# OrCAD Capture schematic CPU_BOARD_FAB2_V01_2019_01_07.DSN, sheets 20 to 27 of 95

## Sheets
20 071 ISOLATOR_1: size B
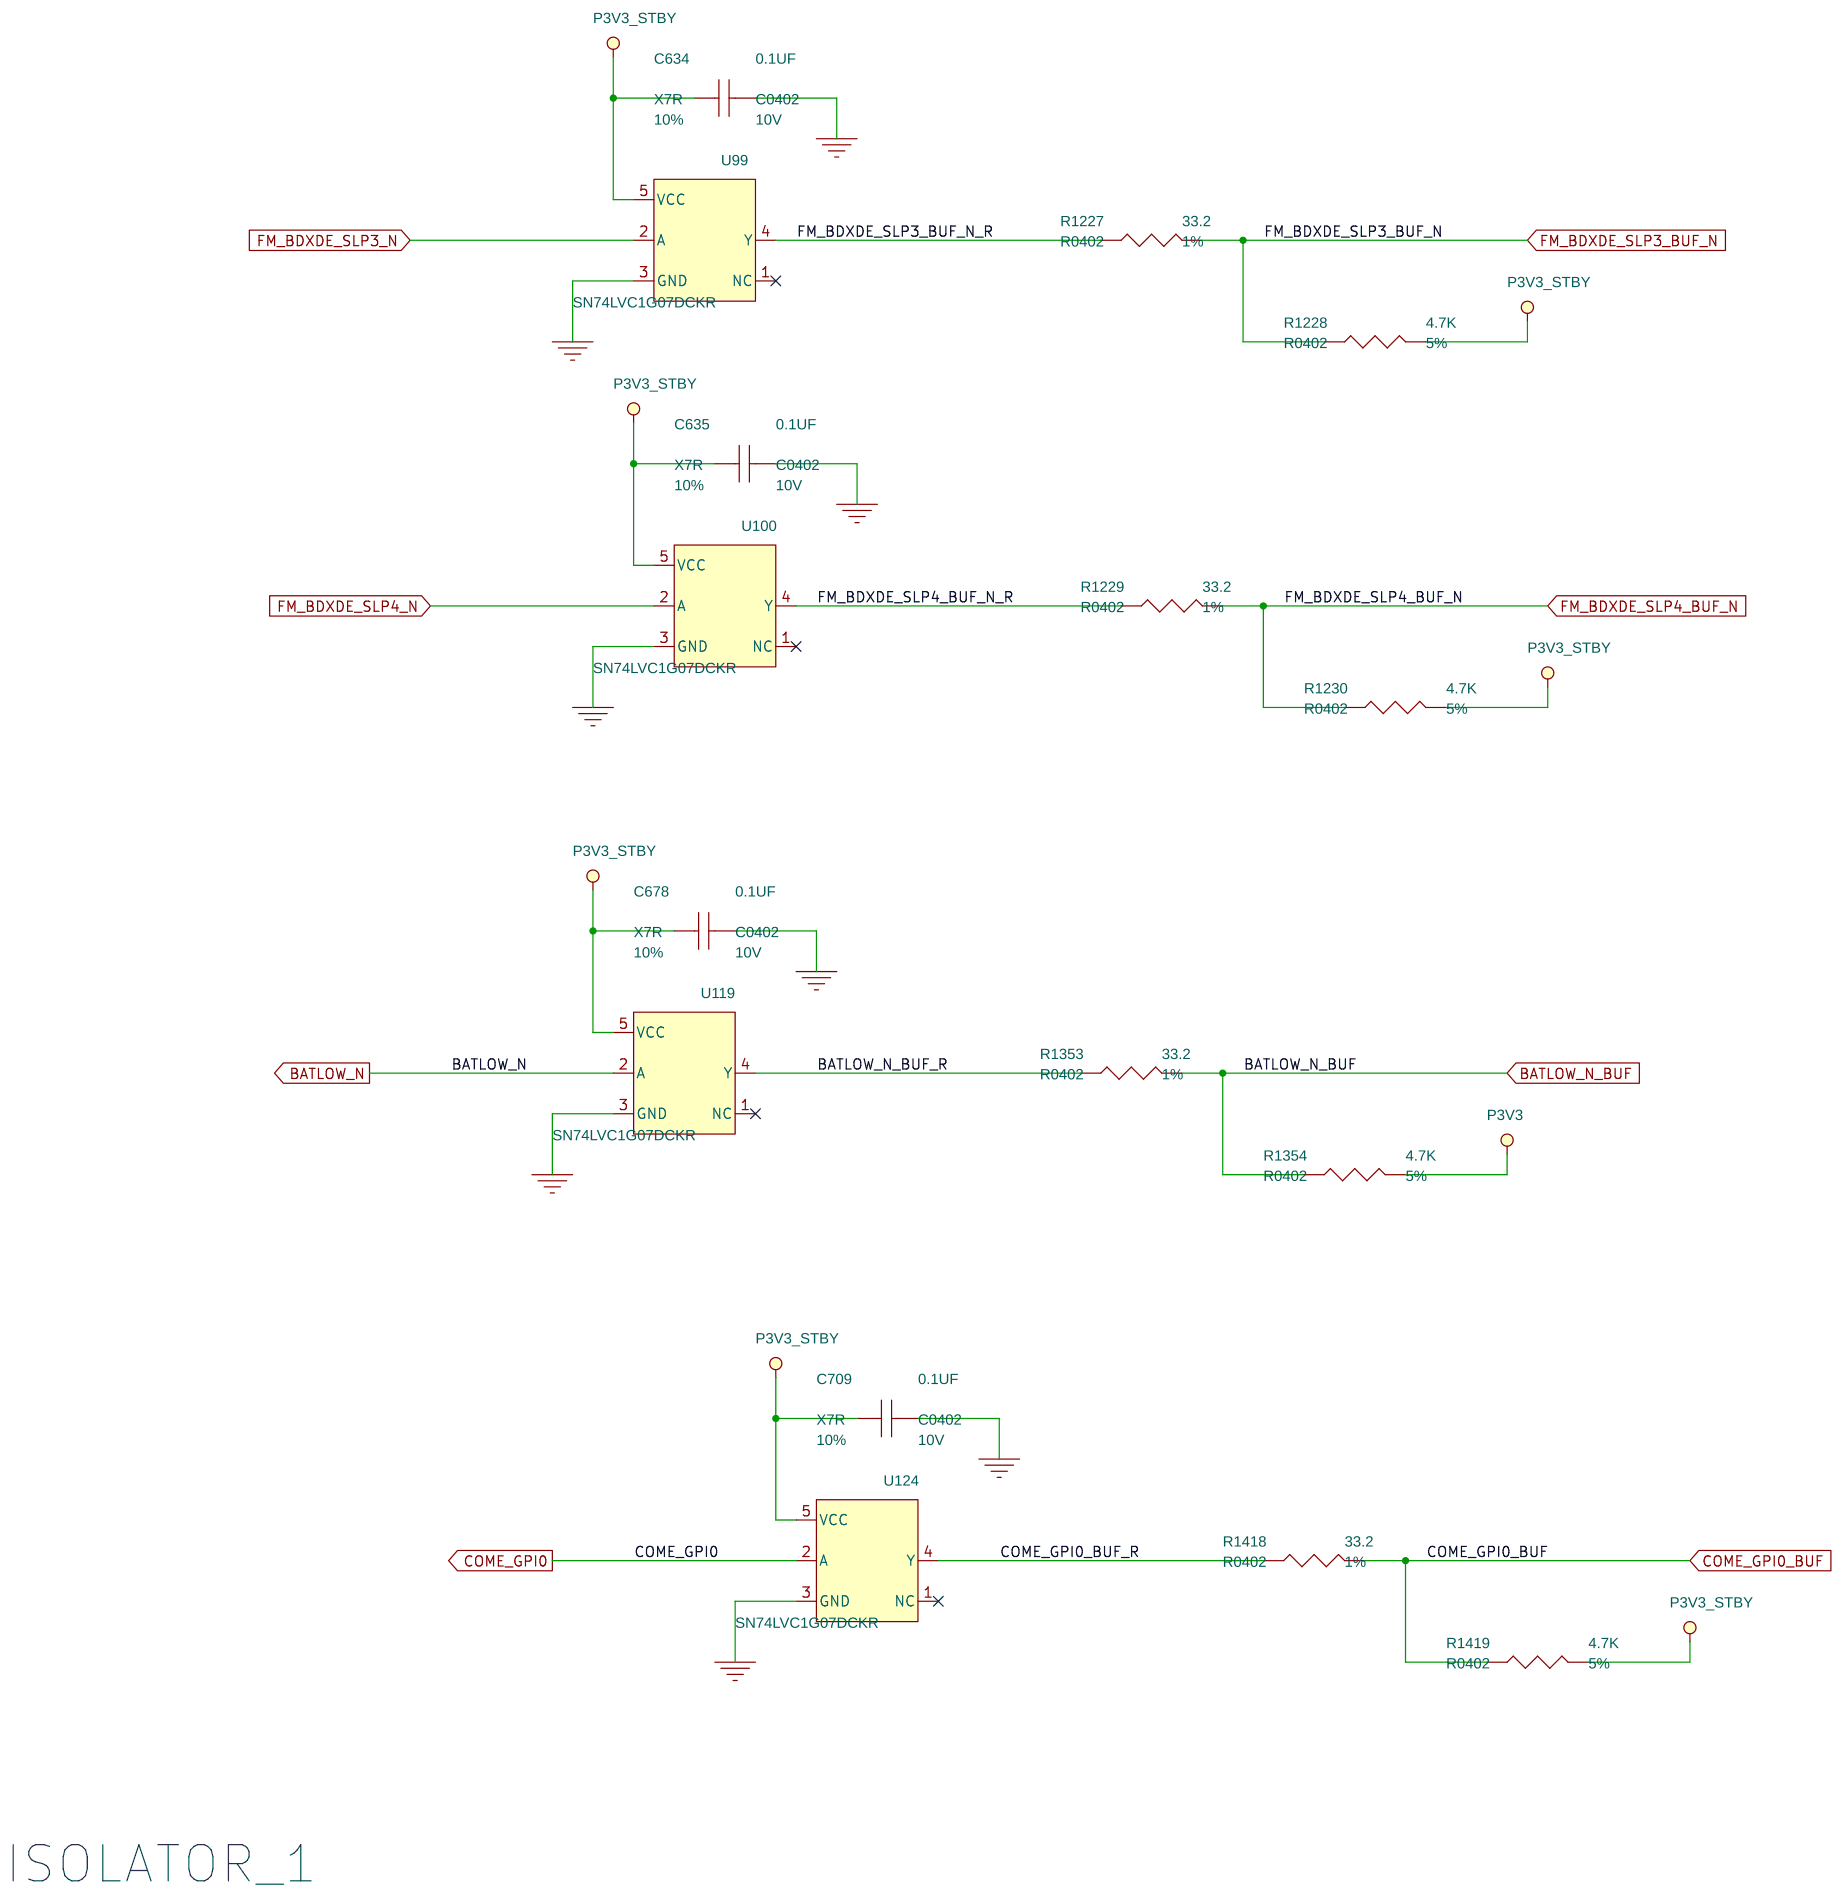
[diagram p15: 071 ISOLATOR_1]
21 015 BLANK
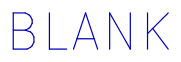
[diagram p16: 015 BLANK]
22 089 PV_DDR_VTTAB: size B
23 088 PV_VDDRAB_2: size B
24 087 PV_VDDRAB_1: size C
25 081 P2V5_VPP: size B
26 082 PVCCKRHV: size B
27 080 PVCCSCFUSESUS: size B
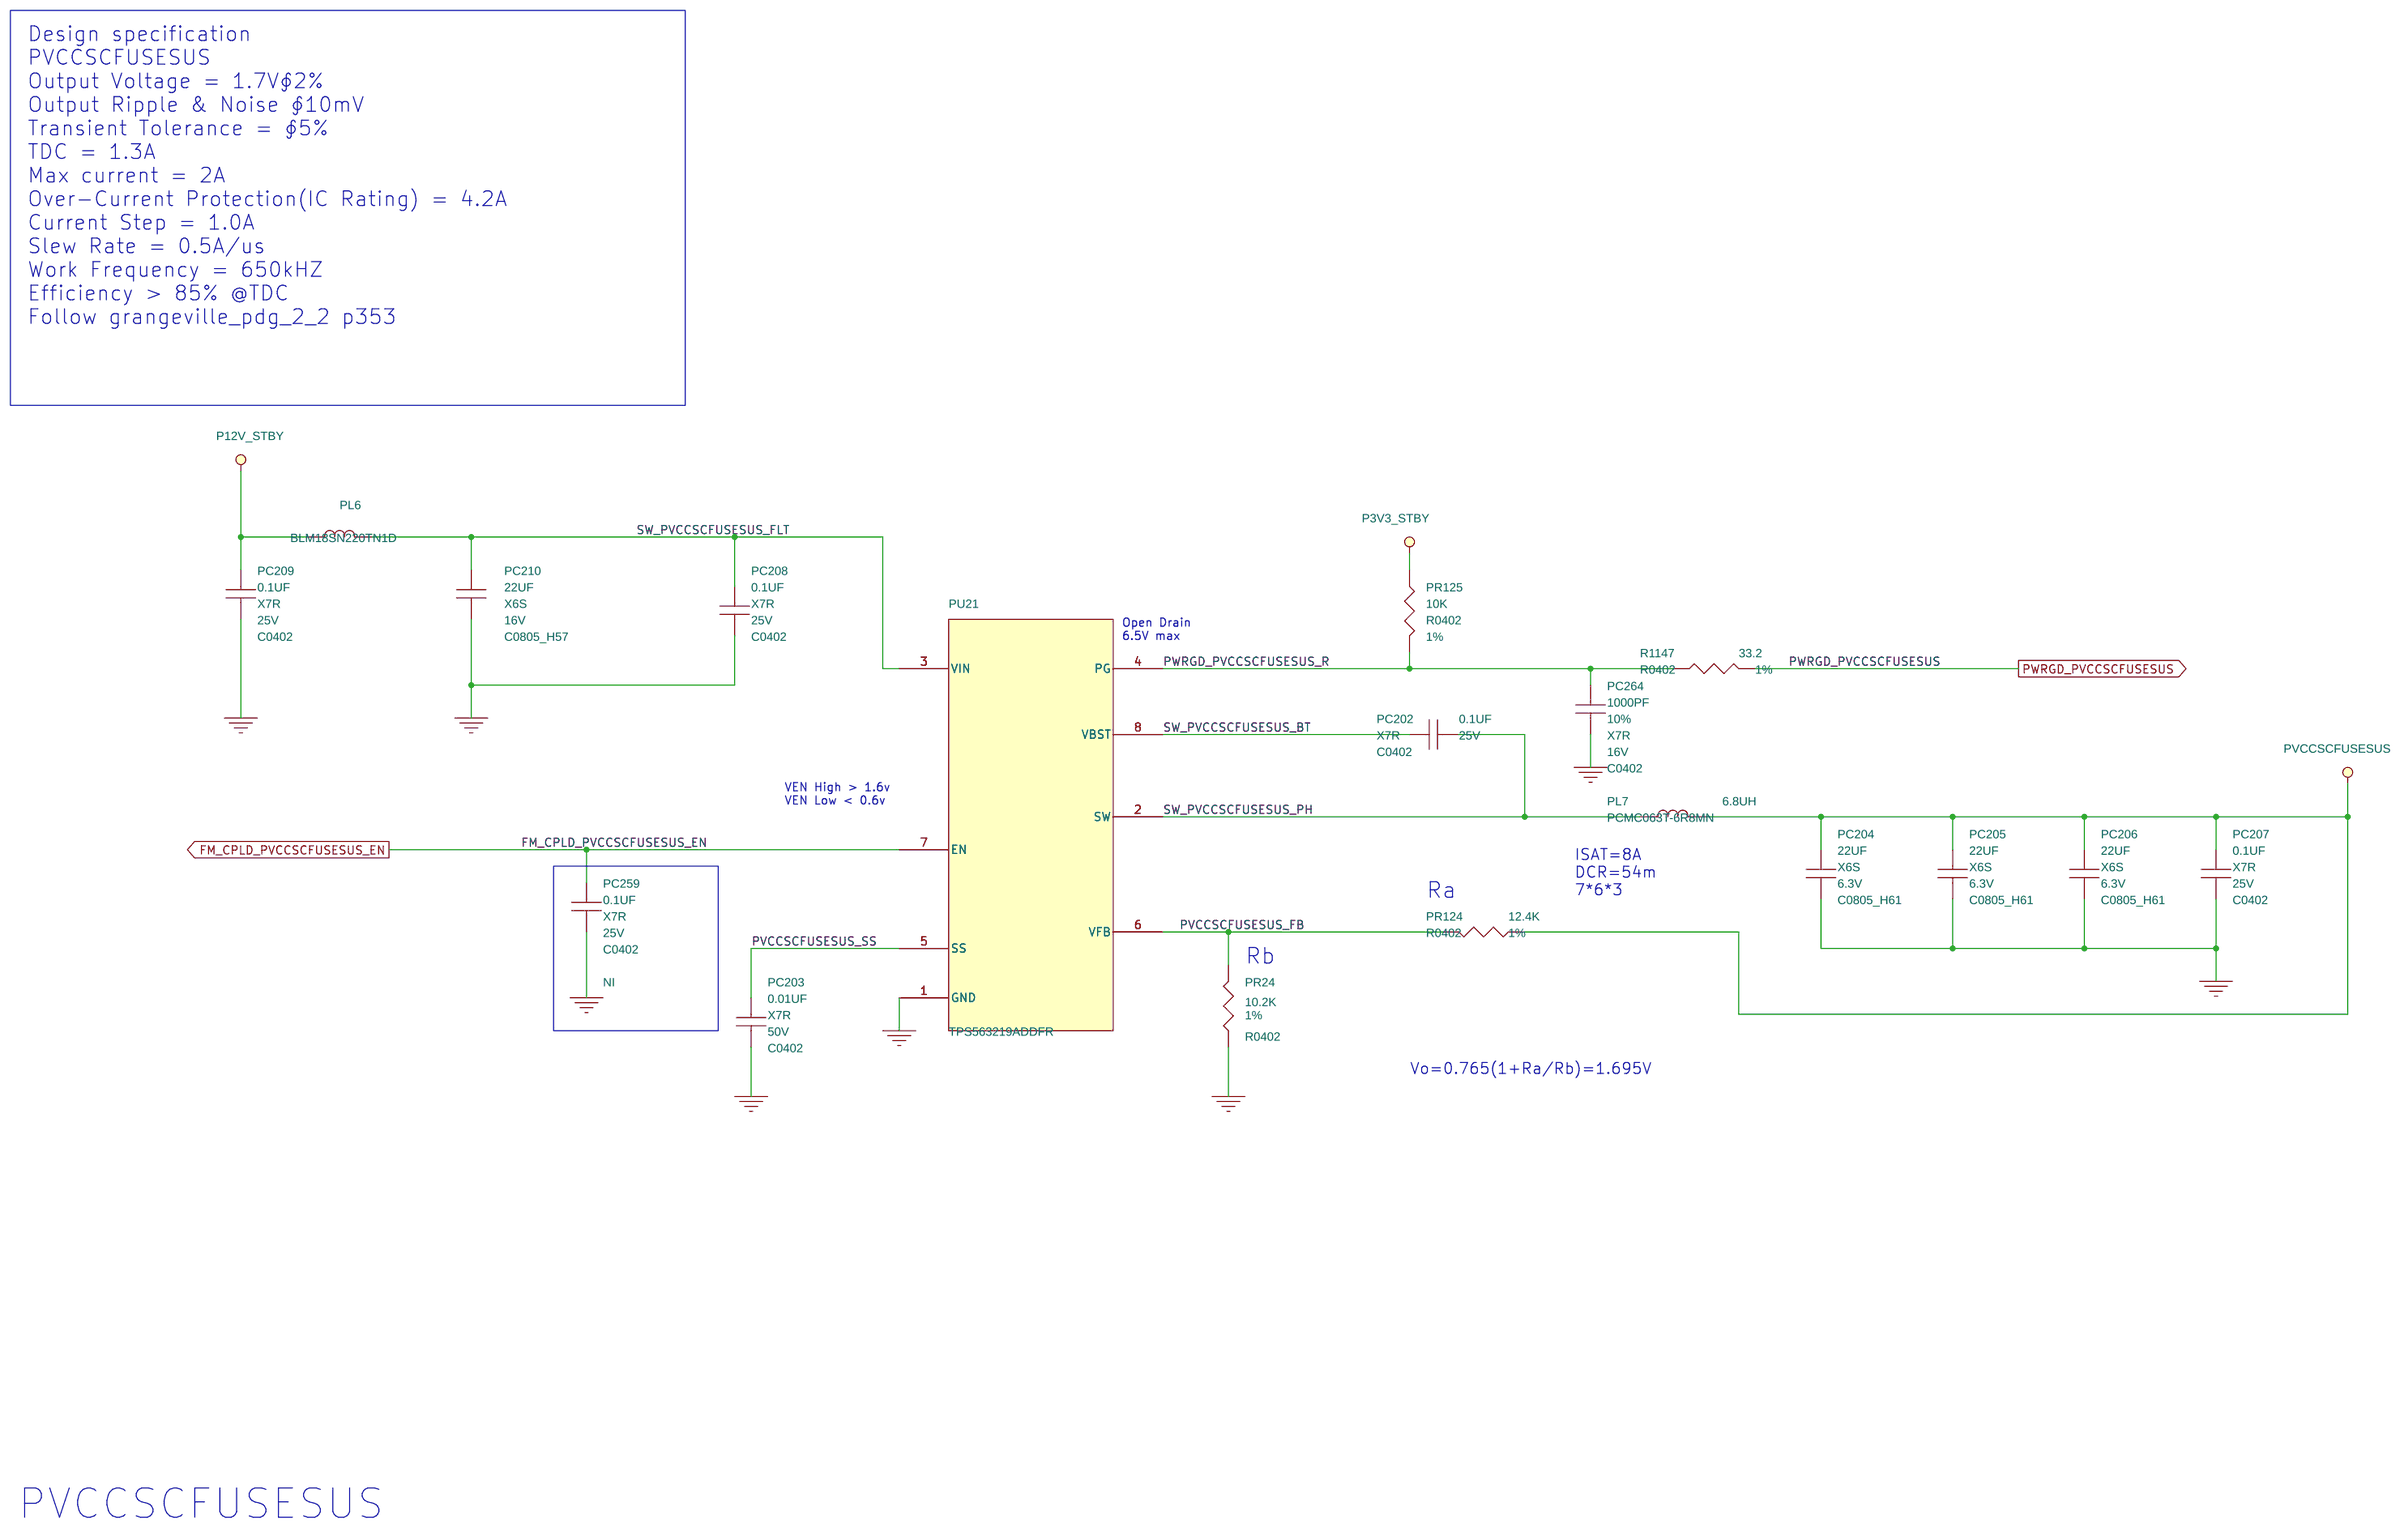
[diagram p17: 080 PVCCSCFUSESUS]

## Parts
sheet 071 ISOLATOR_1
C634  0.1UF  [C0402]
C635  0.1UF  [C0402]
C678  0.1UF  [C0402]
C709  0.1UF  [C0402]
R1227  33.2  [R0402]
R1228  4.7K  [R0402]
R1229  33.2  [R0402]
R1230  4.7K  [R0402]
R1353  33.2  [R0402]
R1354  4.7K  [R0402]
R1418  33.2  [R0402]
R1419  4.7K  [R0402]
U99  SN74LVC1G07DCKR  [SC70-5XB]
U100  SN74LVC1G07DCKR  [SC70-5XB]
U119  SN74LVC1G07DCKR  [SC70-5XB]
U124  SN74LVC1G07DCKR  [SC70-5XB]
sheet 080 PVCCSCFUSESUS
PC202  0.1UF  [C0402]
PC203  0.01UF  [C0402]
PC204  22UF  [C0805_H61]
PC205  22UF  [C0805_H61]
PC206  22UF  [C0805_H61]
PC207  0.1UF  [C0402]
PC208  0.1UF  [C0402]
PC209  0.1UF  [C0402]
PC210  22UF  [C0805_H57]
PC259  0.1UF  [C0402]
PC264  1000PF  [C0402]
PL6  BLM18SN220TN1D  [L0603]
PL7  6.8UH  [L_PCMC063T]
PR24  10.2K  [R0402]
PR124  12.4K  [R0402]
PR125  10K  [R0402]
PU21  TPS563219ADDFR  [SOT23-8_0-65_2-9X1-6XA]
R1147  33.2  [R0402]
sheet 081 P2V5_VPP
PC192  0.1UF  [C0402]
PC193  0.01UF  [C0402]
PC194  22UF  [C0805_H61]
PC195  22UF  [C0805_H61]
PC196  22UF  [C0805_H61]
PC197  0.1UF  [C0402]
PC198  0.1UF  [C0402]
PC199  0.1UF  [C0402]
PC200  22UF  [C0805_H57]
PC262  0.1UF  [C0402]
PC265  1000PF  [C0402]
PL4  BLM18SN220TN1D  [L0603]
PL5  6.8UH  [L_PCMC063T]
PR120  10.2K  [R0402]
PR121  23.2K  [R0402]
PR122  10K  [R0402]
PU6  TPS563219ADDFR  [SOT23-8_0-65_2-9X1-6XA]
R1167  33.2  [R0402]
sheet 082 PVCCKRHV
PC31  0.1UF  [C0402]
PC41  10UF  [C0805_H57]
PC44  1UF  [C0402]
PC105  22UF  [C0805_H61]
PC260  0.1UF  [C0402]
PR17  10K  [R0402]
PR18  12K  [R0402]
PR19  7.5K  [R0402]
PU9  RT9059GQW  [DFN10_THXE]
R1148  33.2  [R0402]
sheet 087 PV_VDDRAB_1
C612  0.1UF  [C0402]
PC214  2200PF  [C0402]
PC215  1UF  [C0402]
PC216  1UF  [C0402]
PC218  1UF  [C0402]
PJ3  SHORT  [SHORT_R0603]
PR25  1K  [R0402]
PR28  0  [R0402]
PR29  1  [R0402]
PR127  1K  [R0402]
PR128  66.5K  [R0402]
PR130  37.4K  [R0402]
PR131  4.99  [R0402]
PR132  200  [R0402]
PR1414  1K  [R0402]
PU8  TPS53622ARSBR  [QFN40_THXL]
R1161  33.2  [R0402]
R1363  33.2  [R0402]
R1432  33.2  [R0402]
R1433  33.2  [R0402]
sheet 088 PV_VDDRAB_2
PC78  22UF  [C0805_H61]
PC79  470UF  [TAJ_DXC]
PC80  470UF  [TAJ_DXC]
PC220  33UF  [TAJ_B2XA]
PC221  22UF  [C0805_H57]
PC222  22UF  [C0805_H57]
PC223  22UF  [C0805_H57]
PC224  22UF  [C0805_H61]
PC225  0.1UF  [C0402]
PC226  0.1UF  [C0402]
PC227  0.1UF  [C0402]
PC228  2.2UF  [C0402]
PC229  3300PF  [C0402]
PL18  BLM18SN220TN1D  [L0603]
PL19  330NH  [L_HCUVD6270_6-2X5-5]
PR133  270K  [R0402]
PR1416  3.3  [R0402]
PU22  CSD59958QVM  [QFN13_4X5]
sheet 089 PV_DDR_VTTAB
PC17  10UF  [C0805_H57]
PC23  0.1UF  [C0402]
PC172  10UF  [C0805_H61]
PC173  0.1UF  [C0402]
PC174  1000PF  [C0402]
PC176  0.1UF  [C0402]
PC177  1000PF  [C0402]
PC179  10UF  [C0805_H57]
PC180  10UF  [C0805_H57]
PC181  10UF  [C0805_H57]
PC182  10UF  [C0805_H57]
PJ14  SHORT  [SHORT_R0603_M]
R828  10.2K  [R0402]
R829  10K  [R0402]
R830  10K  [R0402]
R1171  33.2  [R0402]
U77  TPS51200  [DFN10_THXB]

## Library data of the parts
C634 C635 C678 C709 = CAP_NP: CAP CHIP 0.1U 10V(+-10%.X7R.0402); CLASS: DISCRETE; CMPLS_LVL: EP; Data: RHT_LF_CAP SERIES-1.pdf; From_pj: S82-ICE; Lifecycle: Comp-Approve; MATERIAL: X7R; Manuf_PN: GRM155R71A104K; Manuf_name: "MURATA ERIE N.A. INC TAIWAN BRANCH Okayama Murata Mfg.Co..Ltd.Wakura Murata Mfg; Manuftr: MUR; Part_Type: *LF_C0402; Standard: ##; Status: Preferred; TOLERANCE: 10%; VOLTAGE: 10V; fp_ECN: 0402 SERIES_LL34.xls
R1147 R1148 R1161 R1167 R1171 R1227 R1229 R1353 R1418 R1432 R1433 = R: RES CHIP 33.2 1/16W +-1%(0402); CLASS: DISCRETE; CMPLS_LVL: EP; Data: CYN_LF_RL SERIES.pdf; From_pj: A06-EDISON; Lifecycle: Comp-Approve; MATERIAL: CHIP; Manuf_PN: RR0510S-33R2-FN; Manuf_name: CYNTEC CO.. LTD.; Manuftr: CYN; Part_Type: *LF_Resistor; TOLERANCE: 1%; WATTAGE: 1/16W; fp_ECN: 0402 SERIES_LL34.xls
R1228 R1230 R1354 R1419 = R: RES CHIP 4.7K 1/16W +-5% (0402); CLASS: DISCRETE; CMPLS_LVL: EP; Data: WTC_LF_WR SERIES.pdf; Lifecycle: Comp-Approve; MATERIAL: CHIP; Manuf_PN: RR0510S-472-JN; Manuf_name: CYNTEC CO.. LTD.; Manuftr: CYN; Part_Type: *LF_Resistor; Status: Preferred; TOLERANCE: 5%; WATTAGE: 1/16W; fp_ECN: 0402 SERIES_LL34.xls
U99 U100 U119 U124 = SN74LVC1G07: IC OTHER(5P)SN74LVC1G07DCKR(SOT); CLASS: IC; CMPLS_LVL: EP(V1); Data: TIC_SN74LVC1G07DCKR.pdf; From_pj: S50-STEVE; Lifecycle: Comp-Approve; MATERIAL: IC; Manuf_name: TEXAS INSTRUMENTS SUPPLY CO..; Manufacturer: TIC; Manuftr: TIC; Part_Type: *LF_Chipset; RD_CMPLS_LVL: EP(V1); Standard: Potential
PC192 PC202 = CAP_NP: CAP CHIP 0.1U 25V(+-10%,X7R,0402); CLASS: DISCRETE; Data: YGO_CA-CC-SC SERIES.pdf; From_pj: F03-KC; Lifecycle: Comp-Approve; MATERIAL: X7R; Manuf_PN: CC0402KRX7R8BB104; Manuf_name: YAGEO CORPORATION; Manufacturer: RHT; Manuftr: YGO; Part_Type: *LF_C0402; RD_CMPLS_LVL: EP(V1); REUSE_ANNOTATE: TRUE; SIDE: BOT; Standard: End of Design; TOLERANCE: 10%; VOLTAGE: 25V; fp_ECN: 0402 SERIES_LL34.xls
PC193 PC203 = CAP_NP: CAP CHIP 0.01U 50V(+-10%,X7R,0402); CLASS: DISCRETE; CMPLS_LVL: EP(V1); Data: MUR_MLCC_20110826.pdf; From_pj: T2B-CHEESE; Lifecycle: Comp-Approve; MATERIAL: X7R; Manuf_PN: WBM155R71H103K; Manuf_name: MURATA ERIE N.A. INC TAIWAN BRANCH Okayama Murata Mfg.Co.,Ltd.; Manufacturer: AVX; Manuftr: MUR; Part_Type: *LF_C0402; RD_CMPLS_LVL: EP(V1); REUSE_ANNOTATE: TRUE; SIDE: TOP; TOLERANCE: 10%; Top_Bot: BOT; VOLTAGE: 50V; fp_ECN: 0402 SERIES_LL34.xls
PC194-PC196 PC204-PC206 = CAP_NP: CAP CHIP 22U 6.3V(+-20%,X6S,0805)MUR; CLASS: DISCRETE; CMPLS_LVL: EP(V1); Data: GRM21BC80J226M.pdf; From_pj: T2H-CF; Lifecycle: Comp-Approve; MATERIAL: X6S; Manuf_PN: GRM21BC80J226M; Manuf_name: MURATA ERIE N.A. INC TAIWAN BRANCH Okayama Murata Mfg.Co.,Ltd.Wakura Murata Mfg.; Manufacturer: AVX; Manuftr: MUR; Part_Type: *LF_C0805; RD_CMPLS_LVL: EP(V1); REUSE_ANNOTATE: TRUE; SIDE: TOP; Standard: End of Design; TOLERANCE: 20%; Top_Bot: BOT; VOLTAGE: 6.3V
PC197 PC207 = CAP_NP: CAP CHIP 0.1U 25V(+-10%,X7R,0402); CLASS: DISCRETE; Data: YGO_CA-CC-SC SERIES.pdf; From_pj: F03-KC; Lifecycle: Comp-Approve; MATERIAL: X7R; Manuf_PN: CC0402KRX7R8BB104; Manuf_name: YAGEO CORPORATION; Manufacturer: AVX; Manuftr: YGO; Part_Type: *LF_C0402; RD_CMPLS_LVL: EP(V1); REUSE_ANNOTATE: TRUE; SIDE: TOP; Standard: End of Design; TOLERANCE: 10%; Top_Bot: BOT; VOLTAGE: 25V; fp_ECN: 0402 SERIES_LL34.xls
PC198 PC208 = CAP_NP: CAP CHIP 0.1U 25V(+-10%,X7R,0402); CLASS: DISCRETE; Data: YGO_CA-CC-SC SERIES.pdf; From_pj: F03-KC; Lifecycle: Comp-Approve; MATERIAL: X7R; Manuf_PN: CC0402KRX7R8BB104; Manuf_name: YAGEO CORPORATION; Manufacturer: MAT; Manuftr: YGO; Part_Type: *LF_C0402; RD_CMPLS_LVL: EP(V1); REUSE_ANNOTATE: TRUE; Standard: End of Design; TOLERANCE: 10%; VOLTAGE: 25V; fp_ECN: 0402 SERIES_LL34.xls
PC199 PC209 PC225 = CAP_NP: CAP CHIP 0.1U 25V(+-10%,X7R,0402); CLASS: DISCRETE; Data: YGO_CA-CC-SC SERIES.pdf; From_pj: F03-KC; Lifecycle: Comp-Approve; MATERIAL: X7R; Manuf_PN: CC0402KRX7R8BB104; Manuf_name: YAGEO CORPORATION; Manufacturer: MAT; Manuftr: YGO; Part_Type: *LF_C0402; RD_CMPLS_LVL: EP(V1); REUSE_ANNOTATE: TRUE; SIDE: TOP; Standard: End of Design; TOLERANCE: 10%; Top_Bot: TOP; VOLTAGE: 25V; fp_ECN: 0402 SERIES_LL34.xls
PC200 PC210 = CAP_NP: CAP CHIP 22U 16V(+-20%,X6S,0805); CLASS: DISCRETE; Data: MUR_GRM21BC81C226ME44L.pdf; From_pj: F08-ATLUS; Lifecycle: Comp-Approve; MATERIAL: X6S; Manuf_PN: GRM21BC81C226M; Manuf_name: MURATA ERIE N.A. INC TAIWAN BRANCH Okayama Murata Mfg.Co.,Ltd.Wakura Murata Mfg.; Manufacturer: MAT; Manuftr: MUR; Part_Type: *LF_C0805; RD_CMPLS_LVL: EP(V1); REUSE_ANNOTATE: TRUE; TOLERANCE: 20%; VOLTAGE: 16V
PC259 PC260 PC262 = CAP_NP: CAP CHIP 0.1U 25V(+-10%,X7R,0402); CLASS: DISCRETE; Data: YGO_CA-CC-SC SERIES.pdf; From_pj: F03-KC; Lifecycle: Comp-Approve; MATERIAL: X7R; Manuf_PN: CC0402KRX7R8BB104; Manuf_name: YAGEO CORPORATION; Manufacturer: MAT; Manuftr: YGO; Not_insert: NI; Part_Type: *LF_C0402; RD_CMPLS_LVL: EP(V1); REUSE_ANNOTATE: TRUE; SIDE: TOP; Standard: End of Design; TOLERANCE: 10%; Top_Bot: TOP; VOLTAGE: 25V; fp_ECN: 0402 SERIES_LL34.xls
PC264 PC265 = CAP_NP: CAP CHIP 1000PF 16V (+-10%,X7R,0402)MUR; CLASS: DISCRETE; CMPLS_LVL: EP(V1); From_pj: T2H-CF; Lifecycle: Comp-Approve; MATERIAL: X7R; Manuf_PN: WBM155R71C102K; Manuf_name: MURATA ERIE N.A. INC TAIWAN BRANCH Okayama Murata Mfg.Co.,Ltd.Wakura Murata Mfg.; Manuftr: MUR; Part_Type: *LF_C0402; RD_CMPLS_LVL: EP(V1); TOLERANCE: 10%; VOLTAGE: 16V
PL4 PL6 PL18 = L: EMI FILTER BLM18SN220TN1D(22,8000MA); CLASS: DISCRETE; Current_Amp: 8000MA; Data: MUR_BLM18SN220TN1D.pdf; From_pj: F08-ATLUS; Lifecycle: Comp-Approve; MATERIAL: IND; Manuf_name: MURATA ERIE N.A. INC TAIWAN BRANCH Okayama Murata Mfg.Co.,; Manuftr: MUR; Part_Type: *LF_Inductor; RD_CMPLS_LVL: EP(V1); SIDE: TOP
PL5 PL7 = L: IND SMD 6.8UH +-20%,4.5A(PCMC063T-6R8MN); CLASS: DISCRETE; Current_Amp: 4.5A; Data: CYN_PCMC063T-000_A4.pdf; From_pj: XG6-KC; Lifecycle: Comp-Approve; MATERIAL: IND; Manuf_PN: PCMC063T-6R8MN; Manuf_name: CYNTEC CO., LTD.; Manuftr: CYN; Part_Type: *LF_Inductor; RD_CMPLS_LVL: EP(V1); Standard: ##; fp_ECN: L_PCMC063T.doc
PR24 = R: RES CHIP 10.2K 1/16W +-1%(0402); CLASS: DISCRETE; CMPLS_LVL: EP; Data: YGO_RC SERIES_1.pdf; From_pj: S75T-TERRY; MATERIAL: CHIP; Manuf_PN: RC0402FR-0710K2L; Manuf_name: YAGEO CORPORATION; Manuftr: YGO; Part_Type: *LF_Resistor; SIDE: TOP; TOLERANCE: 1%; WATTAGE: 1/16W; fp_ECN: 0402 SERIES_LL34.xls
PR124 = R: RES CHIP 12.4K 1/16W +-1% (0402); CLASS: DISCRETE; CMPLS_LVL: PF(V1); Data: RHT_LF_RES SERIES-2.pdf; From_pj: S99Q-JACK; Lifecycle: Comp-Approve; MATERIAL: CHIP; Manuf_PN: CR0212K4F002S; Manuf_name: RTECH TECHNOLOGY CO..LTD.(Compostar); Manuftr: RHT; Part_Type: *LF_Resistor; SIDE: TOP; Standard: ##; TOLERANCE: 1%; WATTAGE: 1/16W; fp_ECN: 0402 SERIES_LL34.xls
PR17 PR122 PR125 = R: RES CHIP 10K 1/16W +-1% (0402); CLASS: DISCRETE; CMPLS_LVL: EP; Data: WTC_LF_WR SERIES.pdf; From_pj: S82; Lifecycle: Comp-Approve; MATERIAL: CHIP; Manuf_PN: RR0510S-103-FN; Manuf_name: CYNTEC CO.. LTD.; Manufacturer: CYN; Manuftr: CYN; Part_Type: *LF_Resistor; Status: Preferred; TOLERANCE: 1%; WATTAGE: 1/16W; fp_ECN: 0402 SERIES_LL34.xls
PU6 PU21 = TPS563219DDFR: IC OTHER(8P)TPS563219ADDFR(SOT-23-THIN); CLASS: IC; Data: TIC_TPS563219ADDFR.pdf; From_pj: S5G-KENNETH; Lifecycle: Comp-Release Qty; MATERIAL: IC; Manuf_name: TEXAS INSTRUMENTS SUPPLY CO.,; Manuftr: TIC; Part_Type: *LF_Chipset; RD_CMPLS_LVL: EP(V1); Standard: Potential
PR120 = R: RES CHIP 10.2K 1/16W +-1%(0402); CLASS: DISCRETE; CMPLS_LVL: EP; Data: YGO_RC SERIES_1.pdf; From_pj: S75T-TERRY; Lifecycle: Comp-Approve; MATERIAL: CHIP; Manuf_PN: RC0402FR-0710K2L; Manuf_name: YAGEO CORPORATION; Manuftr: YGO; Part_Type: *LF_Resistor; SIDE: TOP; TOLERANCE: 1%; WATTAGE: 1/16W; fp_ECN: 0402 SERIES_LL34.xls
PR121 = R: RES CHIP 23.2K 1/16W +-1%(0402); CLASS: DISCRETE; CMPLS_LVL: PF(V1); Data: YGO_RC SERIES_1.pdf; From_pj: S99Q-JACK; Lifecycle: Comp-Approve; MATERIAL: CHIP; Manuf_PN: RC0402FR-0723K2L; Manuf_name: YAGEO CORPORATION; Manuftr: YGO; Part_Type: *LF_Resistor; SIDE: TOP; TOLERANCE: 1%; WATTAGE: 1/16W; fp_ECN: 0402 SERIES_LL34.xls
PC31 = CAP_NP: CAP CHIP 0.1U 16V(10%.X7R.0402); CLASS: DISCRETE; CMPLS_LVL: EP(V1); Data: MUR_LF_CAP SERIES_1.pdf; From_pj: S5A-TRAVIS; Lifecycle: Comp-Approve; MATERIAL: X7R; Manuf_PN: WBM155R71C104K; Manuf_name: MURATA ERIE N.A. INC TAIWAN BRANCH Okayama Murata Mfg.Co..Ltd. Wakura Murata Mfg; Manufacturer: AVX; Manuftr: MUR; Part_Type: *LF_C0402; RD_CMPLS_LVL: EP(V1); TOLERANCE: 10%; Top_Bot: BOT; VOLTAGE: 16V; fp_ECN: 0402 SERIES_LL34.xls
PC17 PC41 PC179-PC182 = CAP_NP: CAP CHIP 10U,4V(+-20%,X6S,0805)MUR; CLASS: DISCRETE; CMPLS_LVL: EP(V1); Data: MUR_GRM21BC80G106M.pdf; From_pj: T2H-DUNCAN; Lifecycle: Comp-Approve; MATERIAL: X6S; Manuf_PN: GRM21BC80G106M; Manuf_name: MURATA ERIE N.A. INC TAIWAN BRANCH Okayama Murata Mfg.Co..Ltd.Wakura Murata Mfg.; Manuftr: MUR; Part_Type: *LF_C0805; RD_CMPLS_LVL: EP(V1); TOLERANCE: 20%; VOLTAGE: 4V
PC44 = CAP_NP: CAP CHIP 1UF 10V(+-10%,X6S,0402); CLASS: DISCRETE; CMPLS_LVL: EP(V1); Data: MUR_LF_CAPSERIES_19JUN2012.pdf; From_pj: T6M-MARKCHEN; Lifecycle: Comp-Approve; MATERIAL: X6S; Manuf_PN: GRM155C81A105K; Manuf_name: MURATA ERIE N.A. INC TAIWAN BRANCH Okayama Murata Mfg.Co.,; Manufacturer: AVX; Manuftr: MUR; Part_Type: *LF_C0402; RD_CMPLS_LVL: EP(V1); REUSE_ANNOTATE: TRUE; Standard: End of Design; TOLERANCE: 10%; Top_Bot: BOT; VOLTAGE: 10V; fp_ECN: 0402 SERIES_LL34.xls
PC105 = CAP_NP: CAP CHIP 22U 6.3V(+-20%,X6S,0805)MUR; CLASS: DISCRETE; CMPLS_LVL: EP(V1); Data: GRM21BC80J226M.pdf; From_pj: T2H-CF; Lifecycle: Comp-Approve; MATERIAL: X6S; Manuf_PN: GRM21BC80J226M; Manuf_name: MURATA ERIE N.A. INC TAIWAN BRANCH Okayama Murata Mfg.Co.,Ltd.Wakura Murata Mfg.; Manuftr: MUR; Part_Type: *LF_C0805; RD_CMPLS_LVL: EP(V1); Standard: End of Design; TOLERANCE: 20%; VOLTAGE: 6.3V
PR18 = R: RES CHIP 12K(1/16W.+-1%.0402); CLASS: DISCRETE; CMPLS_LVL: EP; Data: WTC_LF_WR SERIES-4.pdf; From_pj: T96-KC; Lifecycle: Comp-Approve; MATERIAL: CHIP; Manuf_PN: WR04X1202FTL; Manuf_name: WALSIN TECHNOLOGY CORPORATION; Manufacturer: RLC; Manuftr: WTC; Part_Type: *LF_Resistor; TOLERANCE: 1%; TOP_BOT: TOP; WATTAGE: 1/16W; fp_ECN: 0402 SERIES_LL34.xls
PR19 = R: RES CHIP 7.5K 1/16W +-1% (0402); CLASS: DISCRETE; CMPLS_LVL: EP; Data: WTC_LF_WR SERIES-4.pdf; From_pj: S93-MARTIN; Lifecycle: Comp-Approve; MATERIAL: CHIP; Manuf_PN: WR04X7501FTL; Manuf_name: WALSIN TECHNOLOGY CORPORATION; Manufacturer: RLC; Manuftr: WTC; Part_Type: *LF_Resistor; TOLERANCE: 1%; TOP_BOT: TOP; WATTAGE: 1/16W; fp_ECN: 0402 SERIES_LL34.xls
PU9 = RT9059GQW: IC OTHER(10P) RT9059GQW(WDFN); CLASS: IC; Data: RTK_RT9059_rev2012.pdf; From_pj: S4E-ALAN; Lifecycle: Comp-Approve; MATERIAL: IC; Manuf_name: RICHTEK TECHNOLOGY CORPORATION; Manuftr: RTK; Part_Type: *LF_Chipset; RD_CMPLS_LVL: EP(V1)
C612 = CAP_NP: CAP CHIP 0.1U 16V(10%.X7R.0402); CLASS: DISCRETE; CMPLS_LVL: EP(V1); Data: MUR_LF_CAP SERIES_1.pdf; From_pj: S5A-TRAVIS; Lifecycle: Comp-Approve; MATERIAL: X7R; Manuf_PN: WBM155R71C104K; Manuf_name: MURATA ERIE N.A. INC TAIWAN BRANCH Okayama Murata Mfg.Co..Ltd. Wakura Murata Mfg; Manufacturer: MUR; Manuftr: MUR; Not_insert: NI; Part_Type: *LF_C0402; RD_CMPLS_LVL: EP(V1); TOLERANCE: 10%; VOLTAGE: 16V; fp_ECN: 0402 SERIES_LL34.xls; top_bot: TOP
PC214 = CAP_NP: CAP CHIP 2200P 50V(+-10%.X7R.0402); CLASS: DISCRETE; CMPLS_LVL: EP_Tmp; Data: WTC_LF_CAP SERIES-3.pdf; From_pj: T96-KC; Lifecycle: Comp-Approve; MATERIAL: X7R; Manuf_PN: 0402B222K500CT; Manuf_name: WALSIN TECHNOLOGY CORPORATION; Manufacturer: RHT; Manuftr: WTC; Part_Type: *LF_C0402; TOLERANCE: 10%; VOLTAGE: 50V; fp_ECN: 0402 SERIES_LL34.xls
PC215 PC216 PC218 = CAP_NP: CAP CHIP 1UF 25V(+-10%,X6S,0402); CLASS: DISCRETE; CMPLS_LVL: EP(V1); Data: MUR_GRM155R72A221KA01-01.pdf; From_pj: F06-RAYMOND; Lifecycle: Comp-Approve; MATERIAL: X6S; Manuf_PN: GRM155C81E105K; Manuf_name: MURATA ERIE N.A. INC TAIWAN BRANCH Okayama Murata Mfg.Co..Ltd.Wakura Murata Mfg.; Manuftr: MUR; Part_Type: *LF_C0402; RD_CMPLS_LVL: EP(V1); TOLERANCE: 10%; VOLTAGE: 25V; fp_ECN: 0402 SERIES_LL34.xls
PJ3 = JUMPER-2_1: JUMP.SHORT_R0603; CLASS: IO; From_pj: S66-KC; MATERIAL: MECH; Part_Type: Mech
PR25 PR127 = R: RES CHIP 1K 1/16W +-1% (0402); CLASS: DISCRETE; CMPLS_LVL: EP; Data: WTC_LF_WR SERIES.pdf; Lifecycle: Comp-Approve; MATERIAL: CHIP; Manuf_PN: RR0510S-102-FN; Manuf_name: CYNTEC CO.. LTD.; Manuftr: CYN; Part_Type: *LF_Resistor; Status: Preferred; TOLERANCE: 1%; WATTAGE: 1/16W; fp_ECN: 0402 SERIES_LL34.xls
PR28 = R: RESISTOR CHIP 0 1/16W +-5%(0402); CLASS: DISCRETE; CMPLS_LVL: EP; Data: WTC_LF_WR SERIES.pdf; Lifecycle: Comp-Approve; MATERIAL: CHIP; Manuf_PN: RR0510X-000-XN; Manuf_name: CYNTEC CO.. LTD.; Manuftr: CYN; Part_Type: *LF_Resistor; Status: Preferred; TOLERANCE: 5%; WATTAGE: 1/16W; fp_ECN: 0402 SERIES_LL34.xls
PR29 = R: RES CHIP 1 1/16W +-5%(0402); CLASS: DISCRETE; CMPLS_LVL: EP; Data: WTC_LF_WR SERIES.pdf; Lifecycle: Comp-Approve; MATERIAL: CHIP; Manuf_PN: RR0510S-1R0-JN; Manuf_name: CYNTEC CO.. LTD.; Manuftr: CYN; Part_Type: *LF_Resistor; Standard: ##; Status: Preferred; TOLERANCE: 5%; WATTAGE: 1/16W; fp_ECN: 0402 SERIES_LL34.xls
PR128 = R: RES CHIP 66.5K 1/16W +-1%(0402); CLASS: DISCRETE; CMPLS_LVL: PF(V1); Data: YGO_RC SERIES_1.pdf; From_pj: S99W-YAOHSUN; Lifecycle: Comp-Approve; MATERIAL: CHIP; Manuf_PN: RC0402FR-0766K5L; Manuf_name: YAGEO CORPORATION; Manuftr: YGO; Part_Type: *LF_Resistor; Standard: ##; TOLERANCE: 1%; WATTAGE: 1/16W; fp_ECN: 0402 SERIES_LL34.xls
PR130 = R: RES CHIP 37.4K 1/16W +-1% (0402); CLASS: DISCRETE; CMPLS_LVL: EP; Data: RLC_RCT.pdf; From_pj: RS2-EASON; Lifecycle: Comp-Approve; MATERIAL: CHIP; Manuf_PN: RTT023742FTH; Manuf_name: RALEC ELECTRONIC CO.; Manuftr: RLC; Part_Type: *LF_Resistor; TOLERANCE: 1%; WATTAGE: 1/16W; fp_ECN: 0402 SERIES_LL34.xls
PR131 = R: RES CHIP 4.99 1/16W +-1% (0402); CLASS: DISCRETE; CMPLS_LVL: EP(V1); Data: CYN_RL SERIES_revB0.pdf; From_pj: S2B--YU-LIN; Lifecycle: Comp-Approve; MATERIAL: CHIP; Manuf_PN: RR0510S-4R99-FN; Manuf_name: CYNTEC CO., LTD.; Manuftr: CYN; Part_Type: *LF_Resistor; RD_CMPLS_LVL: EP(V1); TOLERANCE: 1%; WATTAGE: 1/16W; fp_ECN: 0402 SERIES_LL34.xls
PR132 = R: RES CHIP 200 1/16W +-1%(0402); CLASS: DISCRETE; CMPLS_LVL: EP; Data: WTC_LF_WR SERIES-4.pdf; From_pj: S79-C.Y.HUANG; Lifecycle: Comp-Approve; MATERIAL: CHIP; Manuf_PN: WR04X2000FTL; Manuf_name: WALSIN TECHNOLOGY CORPORATION; Manuftr: WTC; Part_Type: *LF_Resistor; TOLERANCE: 1%; WATTAGE: 1/16W; fp_ECN: 0402 SERIES_LL34.xls
PR1414 = R: RES CHIP 1K 1/16W +-1% (0402); CLASS: DISCRETE; CMPLS_LVL: EP; Data: WTC_LF_WR SERIES.pdf; Lifecycle: Comp-Approve; MATERIAL: CHIP; Manuf_PN: RR0510S-102-FN; Manuf_name: CYNTEC CO.. LTD.; Manufacturer: CYN; Manuftr: CYN; Part_Type: *LF_Resistor; Status: Preferred; TOLERANCE: 1%; WATTAGE: 1/16W; fp_ECN: 0402 SERIES_LL34.xls
PU8 = TPS53622ARSBR: IC CTRL(40P)TPS53622ARSBR(WQFN); CLASS: IC; Data: TIC_TPS53622ARSBR.pdf; From_pj: F09-TOUGH-LI; Lifecycle: P/N Release; MATERIAL: IC; Manuf_name: TEXAS INSTRUMENTS SUPPLY CO.,; Manuftr: TIC; Part_Type: *LF_Chipset; RD_CMPLS_LVL: EP(V1); Standard: Potential
R1363 = R: RES CHIP 33.2 1/16W +-1%(0402); CLASS: DISCRETE; CMPLS_LVL: EP; Data: CYN_LF_RL SERIES.pdf; From_pj: A06-EDISON; Lifecycle: Comp-Approve; MATERIAL: CHIP; Manuf_PN: RR0510S-33R2-FN; Manuf_name: CYNTEC CO.. LTD.; Manufacturer: RHT; Manuftr: CYN; Part_Type: *LF_Resistor; TOLERANCE: 1%; WATTAGE: 1/16W; fp_ECN: 0402 SERIES_LL34.xls; top_bot: TOP
PC78 PC224 = CAP_NP: CAP CHIP 22U 4V(+-20%.X6S.0805); CLASS: DISCRETE; CMPLS_LVL: EP; Data: MUR_LF_CAP SERIES_2.pdf; From_pj: S50-STEVE; Lifecycle: Comp-Approve; MATERIAL: X6S; Manuf_PN: GRM21BC80G226M; Manuf_name: MURATA ERIE N.A. INC TAIWAN BRANCH Okayama Murata Mfg.Co..Ltd.Wakura Murata Mfg.; Manuftr: MUR; Part_Type: *LF_C0805; Standard: End of Design; TOLERANCE: 20%; VOLTAGE: 4V
PC79 PC80 = CAPACITOR_POL: CAP CHIP 470U 2V(+-20% ESR=3.7343)H1.9; CLASS: DISCRETE; CMPLS_LVL: EP(V1); Data: EEFGX0D471R.pdf; From_pj: T2B-KC; Lifecycle: Comp-Approve; MATERIAL: POSCAP; Manuf_PN: EEFGX0D471R; Manuf_name: MATSUSHITA ELECTRONICS CORPORATION (PANASONIC)Wuxi Matsushita Battery Co.. Ltd; Manuftr: MAT; Part_Type: *LF_C_POSCAP; RD_CMPLS_LVL: EP(V1); TOLERANCE: 20%; VOLTAGE: 2V
PC220 = CAPACITOR_POL: CAP CHIP 33U 16V(20%,POSCAP,ESR70,3528); CLASS: DISCRETE; CMPLS_LVL: EP(V1); Data: NEC_TEPSLB21C336M8R.pdf; From_pj: F08-ANSON; Lifecycle: Comp-Release Qty; MATERIAL: POSCAP; Manuf_PN: TEPSLB21C336M8R; Manuf_name: NEC HONG KONG LIMITENEC LCD Technologies, Ltd; Manuftr: NEC; Part_Type: *LF_C_POSCAP; RD_CMPLS_LVL: EP(V1); TOLERANCE: 20%; VOLTAGE: 16V
PC221-PC223 = CAP_NP: CAP CHIP 22U 16V(+-20%,X6S,0805); CLASS: DISCRETE; Data: MUR_GRM21BC81C226ME44L.pdf; From_pj: F08-ATLUS; Lifecycle: Comp-Approve; MATERIAL: X6S; Manuf_PN: GRM21BC81C226M; Manuf_name: MURATA ERIE N.A. INC TAIWAN BRANCH Okayama Murata Mfg.Co.,Ltd.Wakura Murata Mfg.; Manuftr: MUR; Part_Type: *LF_C0805; RD_CMPLS_LVL: EP(V1); TOLERANCE: 20%; VOLTAGE: 16V
PC226 PC227 = CAP_NP: CAP CHIP 0.1U 25V(+-10%,X7R,0402); CLASS: DISCRETE; Data: YGO_CA-CC-SC SERIES.pdf; From_pj: F03-KC; Lifecycle: Comp-Approve; MATERIAL: X7R; Manuf_PN: CC0402KRX7R8BB104; Manuf_name: YAGEO CORPORATION; Manuftr: YGO; Part_Type: *LF_C0402; RD_CMPLS_LVL: EP(V1); Standard: End of Design; TOLERANCE: 10%; VOLTAGE: 25V; fp_ECN: 0402 SERIES_LL34.xls
PC228 = CAP_NP: CAP CHIP 2.2UF 10V(+-10%,X6S,0402); CLASS: DISCRETE; CMPLS_LVL: EP(V1); From_pj: S5A-JOSHUA; Lifecycle: Comp-Approve; MATERIAL: X6S; Manuf_PN: GRM155C81A225K; Manuf_name: MURATA ERIE N.A. INC TAIWAN BRANCH Okayama Murata Mfg.Co.,Ltd.Wakura Murata Mfg.; Manufacturer: RHT; Manuftr: MUR; Part_Type: *LF_C0402; RD_CMPLS_LVL: EP(V1); TOLERANCE: 10%; VOLTAGE: 10V
PC229 = CAP_NP: CAP CHIP 3300P 50V(+-10%.X7R.0402); CLASS: DISCRETE; CMPLS_LVL: EP; Data: RHT_LF_CAP SERIES-4.pdf; From_pj: T96-KC; Lifecycle: Comp-Approve; MATERIAL: X7R; Manuf_PN: CC0402X332K3OST; Manuf_name: RTECH TECHNOLOGY CO..LTD.(Compostar); Manuftr: RHT; Part_Type: *LF_C0402; Standard: ##; TOLERANCE: 10%; VOLTAGE: 50V; fp_ECN: 0402 SERIES_LL34.xls
PL19 = L: IND SMD 330NH 10% 28A(HCUVD6270-331QL); CLASS: DISCRETE; Current_Amp: 28A; Data: DTA_HCUVD6270-331QL.pdf; From_pj: S5T-GREG; Lifecycle: P/N Release; MATERIAL: IND; Manuf_PN: HCUVD6270-331QL; Manuf_name: DELTA ELECTRONIC IND. CO., LTD. DELTA ELECTRONICS; Manuftr: DTA; Part_Type: *LF_Inductor; RD_CMPLS_LVL: EP(V1)
PR133 = R: RES CHIP 270K(1/16W.+-5%.0402); CLASS: DISCRETE; CMPLS_LVL: EP(V1); Data: YGO_RC0402 SERIES.pdf; From_pj: TU1B-MARTIN; Lifecycle: Comp-Approve; MATERIAL: CHIP; Manuf_PN: RC0402JR-07270KL; Manuf_name: YAGEO CORPORATION; Manuftr: YGO; Part_Type: *LF_Resistor; RD_CMPLS_LVL: EP(V1); TOLERANCE: 5%; WATTAGE: 1/16W; fp_ECN: 0402 SERIES_LL34.xls
PR1416 = R: RES CHIP 3.3 1/16W +-5%(0402); CLASS: DISCRETE; CMPLS_LVL: EP; Data: WTC_LF_WR SERIES-4.pdf; From_pj: S99-FUJU; Lifecycle: Comp-Approve; MATERIAL: CHIP; Manuf_PN: RC0402JR-073R3L; Manuf_name: WALSIN TECHNOLOGY CORPORATION; Manuftr: YGO; Part_Type: *LF_Resistor; TOLERANCE: 5%; WATTAGE: 1/16W; fp_ECN: 0402 SERIES_LL34.xls
PU22 = CSD59958QVM: IC OTHER(19P)CSD59958QVM(QFN); CLASS: IC; Data: TIC_CSD59958QVM.pdf; From_pj: S5D-HANK; Lifecycle: Comp-Approve; MATERIAL: IC; Manuf_name: TEXAS INSTRUMENTS SUPPLY CO.,; Manuftr: TIC; Part_Type: *LF_Chipset; RD_CMPLS_LVL: EP(V1); Standard: Potential
PC23 PC173 = CAP_NP: CAP CHIP 0.1U 16V(10%.X7R.0402); CLASS: DISCRETE; CMPLS_LVL: EP(V1); Data: MUR_LF_CAP SERIES_1.pdf; From_pj: S5A-TRAVIS; Lifecycle: Comp-Approve; MATERIAL: X7R; Manuf_PN: WBM155R71C104K; Manuf_name: MURATA ERIE N.A. INC TAIWAN BRANCH Okayama Murata Mfg.Co..Ltd. Wakura Murata Mfg; Manufacturer: API; Manuftr: MUR; Part_Type: *LF_C0402; RD_CMPLS_LVL: EP(V1); TOLERANCE: 10%; TOP_BOT: TOP; VOLTAGE: 16V; fp_ECN: 0402 SERIES_LL34.xls
PC172 = CAP_NP: CAP CHIP 10U 25V(+-10%,X6S,0805)MUR; CLASS: DISCRETE; CMPLS_LVL: EP(V1); Data: GRM21BC81E106K.pdf; From_pj: T2H-CF; Lifecycle: Comp-Approve; MATERIAL: X6S; Manuf_PN: GRM21BC81E106K; Manuf_name: MURATA ERIE N.A. INC TAIWAN BRANCH Okayama Murata Mfg.Co.,Ltd.Wakura Murata Mfg.; Manuftr: MUR; Part_Type: *LF_C0805; RD_CMPLS_LVL: EP(V1); TOLERANCE: 10%; VOLTAGE: 25V
PC174 PC177 = CAP_NP: "CAP CHIP 1000PF 16V (+-10%.X7R.0402)EP"; CLASS: DISCRETE; Data: WTC_LF_CAP SERIES-1.pdf; From_pj: S82-SP; Lifecycle: Comp-Approve; MATERIAL: X7R; Manuf_PN: CC0402X102K1OST-S; Manuf_name: "RTECH TECHNOLOGY CO..LTD.(Compostar)"; Manufacturer: API; Manuftr: RHT; Part_Type: *LF_C0402; Status: Preferred; TOLERANCE: 10%; TOP_BOT: TOP; VOLTAGE: 16V; fp_ECN: 0402 SERIES_LL34.xls
PC176 = CAP_NP: CAP CHIP 0.1U 16V(10%.X7R.0402); CLASS: DISCRETE; CMPLS_LVL: EP(V1); Data: MUR_LF_CAP SERIES_1.pdf; From_pj: S5A-TRAVIS; Lifecycle: Comp-Approve; MATERIAL: X7R; Manuf_PN: WBM155R71C104K; Manuf_name: MURATA ERIE N.A. INC TAIWAN BRANCH Okayama Murata Mfg.Co..Ltd. Wakura Murata Mfg; Manufacturer: TAY; Manuftr: MUR; Part_Type: *LF_C0402; RD_CMPLS_LVL: EP(V1); TOLERANCE: 10%; TOP_BOT: TOP; VOLTAGE: 16V; fp_ECN: 0402 SERIES_LL34.xls
PJ14 = JUMPER-2_1: JUMP.SHORT_R0603_M; CLASS: IO; From_pj: KC; MATERIAL: MECH; Part_Type: Mech
R828 = R: RES CHIP 10.2K 1/16W +-1%(0402); CLASS: DISCRETE; CMPLS_LVL: EP; Data: YGO_RC SERIES_1.pdf; From_pj: S75T-TERRY; MATERIAL: CHIP; Manuf_PN: RC0402FR-0710K2L; Manuf_name: YAGEO CORPORATION; Manuftr: YGO; Part_Type: *LF_Resistor; TOLERANCE: 1%; WATTAGE: 1/16W; fp_ECN: 0402 SERIES_LL34.xls
R829 R830 = R: RES CHIP 10K 1/16W +-1% (0402); CLASS: DISCRETE; CMPLS_LVL: EP; Data: WTC_LF_WR SERIES.pdf; From_pj: S82; Lifecycle: Comp-Approve; MATERIAL: CHIP; Manuf_PN: RR0510S-103-FN; Manuf_name: CYNTEC CO.. LTD.; Manuftr: CYN; Part_Type: *LF_Resistor; Status: Preferred; TOLERANCE: 1%; WATTAGE: 1/16W; fp_ECN: 0402 SERIES_LL34.xls
U77 = TPS51200: IC OTHER(10P) TPS51200DRC(SON); CLASS: IC; CMPLS_LVL: EP_Tmp; Data: TIC_TPS51200.pdf; EE_CHECK_LIST: DFN10_THXB.xls; From_pj: S5-KC; MATERIAL: IC; Manuf_PN: TPS51200DRC; Manuf_name: TEXAS INSTRUMENTS SUPPLY CO..; Manuftr: TIC; Part_Type: *LF_Chipset

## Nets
GND: C612.1 C634.2 C635.2 C678.2 C709.2 PC17.2 PC23.2 PC31.2 PC41.2 PC44.2 PC78.2 PC79.2 PC80.2 PC105.2 PC172.2 PC173.2 PC174.2 PC176.2 PC177.2 PC179.2 PC180.2 PC181.2 PC182.2 PC193.2 PC194.2 PC195.2 PC196.2 PC197.2 PC198.2 PC199.2 PC200.2 PC203.2 PC204.2 PC205.2 PC206.2 PC207.2 PC208.2 PC209.2 PC210.2 PC214.2 PC215.2 PC216.2 PC218.2 PC220.2 PC221.2 PC222.2 PC223.2 PC224.2 PC225.2 PC227.2 PC228.2 PC229.2 PC259.2 PC260.2 PC262.2 PC264.2 PC265.2 PR18.1 PR24.1 PR120.1 PR130.2 PR133.2 PU6.1(GND) PU8.3(AVSN) PU8.13(BVR_EN) PU8.28(BVSP) PU8.29(BVSN) PU8.30(BCSP) PU8.TH(AGND) PU9.TH(EP) PU21.1(GND) PU22.19(PGND) R830.2 U77.4(PGND) U77.8(GND) U77.TH(GND-EP) U99.3(GND) U100.3(GND) U119.3(GND) U124.3(GND) ; also on sheet 1 2 3 4 11 12 13 14 15 16 17 18 19 28 31 32 41 42 45 46 47 48 49 50 51 52 53 54 55 56 57 58 59 60 61 62 63 64 65 66 67 68 69 70 71 72 73 74 75 77 79 81 82 83 84 86 87 88 92
P2V5_VPP: PC194.1 PC195.1 PC196.1 PC197.1 PL5.2 PR121.1 ; also on sheet 11 15 19 60 61 75
P2V5_VPP_FB: PR120.2 PR121.2 PU6.6(VFB)
P2V5_VPP_SS: PC193.1 PU6.5(SS)
P3V3: R1354.2 ; also on sheet 4 19 32 41 42 46 47 49 50 52 55 56 63 67 74 77 81
P3V3_STBY: C634.1 C635.1 C678.1 C709.1 PC23.1 PC172.1 PR17.1 PR25.1 PR29.2 PR122.1 PR125.1 PR127.2 PR1414.2 PU8.5(ACSP2) R828.1 R1228.2 R1230.2 R1419.2 U77.10(VIN) U99.5(VCC) U100.5(VCC) U119.5(VCC) U124.5(VCC) ; also on sheet 3 4 13 14 16 18 19 28 31 32 41 52 55 56 57 58 59 62 63 64 65 67 68 69 70 71 72 73 74 75 77 79 81 82 84 86 87 88 92
P5V_STBY: PC44.1 PC227.1 PC228.1 PU9.10(VDD) PU22.4(VDD) PU22.17(EN_FCCM) ; also on sheet 1 2 13 31 70 74 84
P12V_STBY: PC199.1 PC209.1 PC215.1 PC225.1 PL4.1 PL6.1 PL18.2 PU8.11(VIN_CSNIN) PU8.12(CSPIN) ; also on sheet 2 3 28 74 86
PVCCKRHV: PC31.1 PC105.1 PR19.2 PU9.1(VOUT1) PU9.2(VOUT2) PU9.3(VOUT3) ; also on sheet 51
PVCCKRHV_ADJ: PR18.2 PR19.1 PU9.4(ADJ)
PVCCSCFUSESUS: PC41.1 PC204.1 PC205.1 PC206.1 PC207.1 PL7.2 PR124.1 PU9.7(VIN1) PU9.8(VIN2) PU9.9(VIN3) ; also on sheet 31 51
PVCCSCFUSESUS_FB: PR24.2 PR124.2 PU21.6(VFB)
PVCCSCFUSESUS_SS: PC203.1 PU21.5(SS)
PVDDR_VRHOT_N: R1363.2 ; also on sheet 72
PVDDR_VRHOT_N_R: PR127.1 PU8.18(VR_HOT#) R1363.1
BATLOW_N: U119.2(A) ; also on sheet 64 65 71
BATLOW_N_BUF: R1353.2 R1354.1 ; also on sheet 47
BATLOW_N_BUF_R: R1353.1 U119.4(Y)
COME_GPI0: U124.2(A) ; also on sheet 13
COME_GPI0_BUF: R1418.2 R1419.1 ; also on sheet 71
COME_GPI0_BUF_R: R1418.1 U124.4(Y)
FM_BDXDE_SLP3_BUF_N: R1227.2 R1228.1 ; also on sheet 65
FM_BDXDE_SLP3_BUF_N_R: R1227.1 U99.4(Y)
FM_BDXDE_SLP3_N: U99.2(A) ; also on sheet 14 63 64 71
FM_BDXDE_SLP4_BUF_N: R1229.2 R1230.1 ; also on sheet 65
FM_BDXDE_SLP4_BUF_N_R: R1229.1 U100.4(Y)
FM_BDXDE_SLP4_N: U100.2(A) ; also on sheet 63 64 71
FM_CPLD_P0V6_VTT_DIMM_EN: PC176.1 U77.7(EN) ; also on sheet 14
FM_CPLD_P1V2_VDDQ_EN: C612.2 PU8.23(AVR_EN) ; also on sheet 14
FM_CPLD_P2V5_VPP_EN: PC262.1 PU6.7(EN) ; also on sheet 14
FM_CPLD_PVCCKRHV_EN: PC260.1 PU9.6(EN) ; also on sheet 14
FM_CPLD_PVCCSCFUSESUS_EN: PC259.1 PU21.7(EN) ; also on sheet 14
NC_PV_VDDRAB_SMB_ALERT: PU8.25(SMB_ALERT#)
PV_DDR_VTTAB: PC17.1 PC181.1 PC182.1 PJ14.2 U77.3(VO) ; also on sheet 11 15 60 61
PV_VDDRAB: PC78.1 PC79.1 PC80.1 PC179.1 PC180.1 PC224.1 PJ3.1 PL19.2 PU22.5(VOS) R829.1 U77.2(VLDOIN) ; also on sheet 11 15 51 60 61 74
PV_VDDRAB_ADDR: PR128.2 PR130.1 PU8.10(ADDR)
PV_VDDRAB_IMON1: PU8.4(ACSP1) PU22.2(IOUT)
PV_VDDRAB_LSET1: PR133.1 PU22.3(LSET)
PV_VDDRAB_PWM1: PU8.39(APWM1) PU22.16(PWM)
PV_VDDRAB_TSEN: PC214.1 PU8.14(TSEN) PU22.18(TAO_FLT)
PV_VDDRAB_V3P3: PC216.1 PR29.1 PU8.16(V3P3)
PV_VDDRAB_VR_FAULT#: PR1414.1 PU8.27(VR_FAULT#)
PV_VDDRAB_VREF: PC218.1 PR128.1 PU8.1(VREF) PU22.1(REFIN)
PWRGD_P0V6_VTT_DIMM: PC174.1 R1171.1 ; also on sheet 64
PWRGD_P0V6_VTT_DIMM_R: R828.2 R1171.2 U77.9(PGOOD)
PWRGD_P1V2_VDDQ: R1161.1 ; also on sheet 64
PWRGD_P1V2_VDDQ_R: PR25.2 PU8.17(AVR_RDY) R1161.2
PWRGD_P2V5_VPP: R1167.2 ; also on sheet 64
PWRGD_P2V5_VPP_R: PC265.1 PR122.2 PU6.4(PG) R1167.1
PWRGD_PVCCKRHV: R1148.1 ; also on sheet 64
PWRGD_PVCCKRHV_R: PR17.2 PU9.5(PGOOD) R1148.2
PWRGD_PVCCSCFUSESUS: R1147.2 ; also on sheet 64
PWRGD_PVCCSCFUSESUS_R: PC264.1 PR125.2 PU21.4(PG) R1147.1
SH_PV_VDDRAB: PJ3.2 PU8.2(AVSP)
SMB_VR12_PV_VDDRAB_SCL: PU8.24(SMB_CLK) R1432.2
SMB_VR12_PV_VDDRAB_SDA: PU8.26(SMB_DIO) R1433.2
SMB_VR12_SCL_RR: R1432.1 ; also on sheet 3 73
SMB_VR12_SDA_RR: R1433.1 ; also on sheet 3 73
SVID_ALERT_PV_VDDRAB_R: PR28.2 PU8.22(SALERT#)
SVID_CLK_PV_VDDRAB_R: PR132.2 PU8.20(SCLK)
SVID_CPU_ALERT_N: PR28.1 ; also on sheet 3 48
SVID_CPU_CLK: PR132.1 ; also on sheet 3 48
SVID_CPU_DATA: PR131.1 ; also on sheet 3 48
SVID_DIO_PV_VDDRAB_R: PR131.2 PU8.21(SDIO)
SW_P2V5_VPP_BT: PC192.1 PU6.8(VBST)
SW_P2V5_VPP_FLT: PC198.1 PC200.1 PL4.2 PU6.3(VIN)
SW_P2V5_VPP_PH: PC192.2 PL5.1 PU6.2(SW)
SW_P12V_PV_VDDRAB_FLT: PC220.1 PC221.1 PC222.1 PC223.1 PC229.1 PL18.1 PU22.10_13(VIN)
SW_PV_VDDRAB_BOOT1: PC226.1 PU22.15(BOOT)
SW_PV_VDDRAB_BOOT1C: PC226.2 PR1416.2
SW_PV_VDDRAB_BOOTR1: PR1416.1 PU22.14(BOOTR)
SW_PV_VDDRAB_SW1: PL19.1 PU22.6_9(SW)
SW_PVCCSCFUSESUS_BT: PC202.1 PU21.8(VBST)
SW_PVCCSCFUSESUS_FLT: PC208.1 PC210.1 PL6.2 PU21.3(VIN)
SW_PVCCSCFUSESUS_PH: PC202.2 PL7.1 PU21.2(SW)
VR_PVTT_REFIN: PC177.1 R829.2 R830.1 U77.1(REFIN)
VR_PVTT_REFOUT: PC173.1 U77.6(REFOUT)
VR_PVTT_VOSNS: PJ14.1 U77.5(VOSNS)

Not connected (* = marked no-connect by the designer): PU8 6(PU3)* 7(NC7)* 8(NC5)* 9(NC3)* 15(BVR_RDY)* 19(NC2)* 31(NC1)* 32(BSKIP#)* 33(BPWM)* 34(NC4)* 35(NC6)* 36(NC8)* 37(NC9)* 38(APWM2)* 40(ASKIP#)*; U99 1(NC)*; U100 1(NC)*; U119 1(NC)*; U124 1(NC)*

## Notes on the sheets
sheet 20
- ISOLATOR_1
sheet 21
- BLANK
sheet 22
- PV_DDR_VTTAB Design specification
  Output Voltage = 0.6075V
  DC (+/- pk) < 15mV
  Total TOL (+/-) < +51mV / -45mV (0.651V/0.555V)
  TDC = 0.3A
  Max current =0.55A
  Slew Rate = 1.53A/us
  PD = (1.215V - 0.6075V) * 0.55A = 0.33W
  Follow grangeville_pdg_2_2 p377
- PV_DDR_VTTAB
sheet 23
- PV_VDDRAB_PHASE1
- DCR=1.46 m£[
  ISAT=28A/100¢XC
  6.2*5.5*7
- POSCAP
  7.3*4.3*2.4
  ESR=3m£[
- POSCAP
  7.3*4.3*2.4
  ESR=3m£[
- PV_VDDRAB_2
sheet 24
- CAD NOTE:
  CAP & DAMPING RS CLOSE DRIVE-END
- PV_VDDRAB Design specification
  Output Voltage = 1.215V
  DC (+/- pk) < 8mV; Vboot=1.2V
  Ripple (+/- pk) < 2.5mV
  Total TOL (+/- pk) < 60mV / -40mV (1.26V/1.16V)
  TDC = 5.93A
  Max current =6.27A
  Over-Current Protection(Max Rating ⊙ 1.3) =8.2A
  Slew Rate = 16.76A/us
  Load step = 5.38A
  Work Frequency = 600kHZ
  Efficiency > 85% @TDC
  Follow grangeville_pdg_2_2 p372
  GVL_Mem_Pwr_Deliv_TP_558333_Rev1_5
- Pull up as EE side
- Pull up as EE side
- Place PJ3 CLOSE TO VR OUPUT
- ROUTE AS DIFF PAIR FROM DIMM CAP
  10MIL TRACE /5MIL SPACING
  CLOSE TO DIMM'S CENTER
- SVID/ I2C  ADDRESS (EE provide addr)
- RAIL        SVID    I2C      UP RES  DOWN RES
  PV_VDDRAB   02H     C8H      66.5K     37.4K
- PV_VDDRAB_1
sheet 25
- Design specification
  P2V5_VPP
  Output Voltage = 2.5V∮75mV
  Output Ripple & Noise ∮25mV
  Transient Tolerance = 2.75V/2.375V
  TDC = 0.816A
  Max current = 0.978A
  Over-Current Protection(IC Rating) = 4.2A
  Current Step = 0.672A
  Slew Rate = 2.97A/us
  Work Frequency = 650kHZ
  Efficiency > 85% @TDC
  Follow grangeville_pdg_2_2 p370
  GVL_Mem_Pwr_Deliv_TP_558333_Rev1_5
- Open Drain
  6.5V max
- VEN High > 1.6v
  VEN Low < 0.6v
- ISAT=8A
  DCR=54m
  7*6*3
- Ra
- Rb
- Vo=0.765(1+Ra/Rb)=2.505V
- P2V5_VPP
sheet 26
- Design specification
  PVCCKRHV
  Output Voltage = 1.3V∮2.1%
  Output Ripple & Noise ∮4mV
  Transient Tolerance = ∮4.0%
  TDC = 0.25A
  Max current = 0.5A
  Current Step = 0.15A
  Slew Rate = 11A/us
  PD=(1.7V-1.3V)*0.25A=0.1W
  Follow grangeville_pdg_2_2 p356
- VEN High > 1.2v
  VEN Low < 0.4v
- Ra
- Rb
- Vnom=0.8(1+Ra/Rb)= 1.3V
- PVCCKRHV
sheet 27
- Design specification
  PVCCSCFUSESUS
  Output Voltage = 1.7V∮2%
  Output Ripple & Noise ∮10mV
  Transient Tolerance = ∮5%
  TDC = 1.3A
  Max current = 2A
  Over-Current Protection(IC Rating) = 4.2A
  Current Step = 1.0A
  Slew Rate = 0.5A/us
  Work Frequency = 650kHZ
  Efficiency > 85% @TDC
  Follow grangeville_pdg_2_2 p353
- Open Drain
  6.5V max
- VEN High > 1.6v
  VEN Low < 0.6v
- ISAT=8A
  DCR=54m
  7*6*3
- Ra
- Rb
- Vo=0.765(1+Ra/Rb)=1.695V
- PVCCSCFUSESUS
